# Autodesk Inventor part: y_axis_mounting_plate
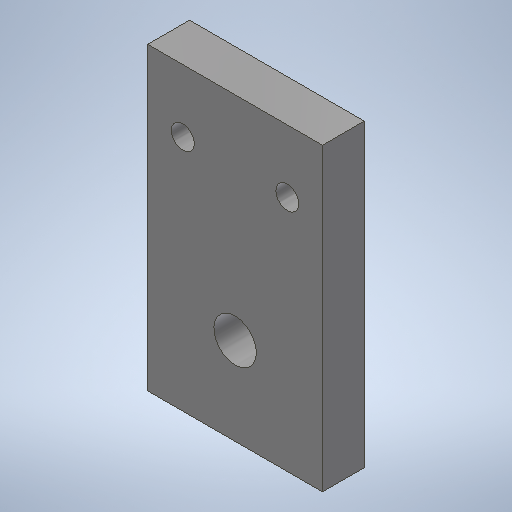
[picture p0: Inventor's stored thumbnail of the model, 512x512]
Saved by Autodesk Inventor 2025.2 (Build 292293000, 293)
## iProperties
Created: 2025-04
Part Number: y_axis_mounting_plate
Material: 1.0037 S235JR
Document SubType Name: Modeling
Designer: BennF
Density: 7.85 g/cm^3
Appearance: Stahl
Author: BennF
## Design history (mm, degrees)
sketch "Sketch2"
  geometry: L1 (20.9, 35.9)-(-20.9, 35.9); L2 (-20.9, 35.9)-(-20.9, -35.9); L3 (-20.9, -35.9)-(20.9, -35.9); L4 (20.9, -35.9)-(20.9, 35.9); 3 further points
  constraints: 8 end point, 2 midpoint, 2 parallel, 1 horizontal, 1 horizontal alignment, 1 perpendicular, 1 vertical alignment
  dimensions: "d0" = 41.8 distance of L2.end L3.end; "d1" = 71.8 distance of L3.end L1.start (computed from d0)
extrude "Extrusion1" new body sketch "Sketch2" distance "d2" = 10; taper "d3" = 0 deg
sketch "Sketch3"
  geometry: L1 (12.5, -20.9)-(-12.5, -20.9); L2 (-20.9, -35.9)-(20.9, -35.9) reference; 2 further points
  constraints: 2 end point, 1 horizontal, 1 horizontal alignment, 1 midpoint, 1 vertical alignment
  dimensions: "d11" = 25 distance of L1.start L1.end; "d12" = 15 distance between parallel lines of L1 L2
hole "Hole1" sketch "Sketch3" at (12.5, -20.9), (-12.5, -20.9) diameter "d4" = 5.5; stored, may be unused: countersink angle "d8" = 90 deg, drill point angle "d10" = 118 deg; dims "d5" = 6, "d6" = 12.5, "d7" = 2, "d9" = 8
workplane "Work Plane1"
sketch "Sketch4"
  geometry: L1 (71.8, 10)-(0, 10) reference; L2 (28.475, 10)-(28.475, 9); L3 (28.475, 9)-(25.975, 9); L4 (25.975, 9)-(25.975, 0); L5 (71.8, 0)-(0, 0) reference; L6 (20.9, 0)-(20.9, 10.187); L7 (0, 0)-(0, 10) reference; 1 further point
  constraints: 8 end point, 3 perpendicular, 2 point on line
  dimensions: "d13" = 10.15 diameter of L4 L6; "d14" = 15.15 diameter of L2 L6; "d15" = 1 distance of L2.start L2.end; "d17" = -20.9 distance between parallel lines of L7 L6
revolve "Revolution1" sketch "Sketch4" stored, may be unused: angle "d16" = 90 deg
body "Solid1"
